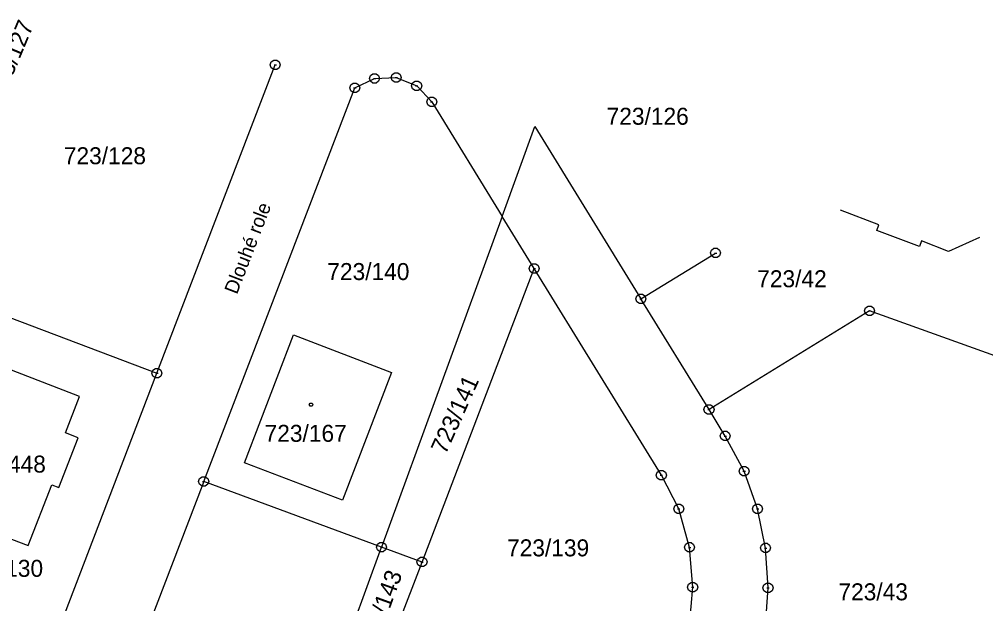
# Model space of a CAD drawing. Extents: x -759060 to -757386, y -1172273 to -1170948.
# Drawn here: x -757575.7 to -757479, y -1171045.6 to -1170987.1 of the extents above; entities that cross this region are included whole.
import ezdxf

# ---------------------------------------------------------------- set-up
doc = ezdxf.new("R2010")
doc.units = 0
for name, color, linetype in [('Vrstva 1', 7, 'Continuous'), ('Vrstva 12', 7, 'Continuous'), ('Vrstva 2', 7, 'Continuous'), ('Vrstva 5', 7, 'Continuous'), ('Vrstva 7', 7, 'Continuous'), ('Vrstva 8', 7, 'Continuous')]:
    doc.layers.add(name, color=color, linetype=linetype)

msp = doc.modelspace()

# ---------------------------------------------------------------- linework, layer by layer
at = {"layer": 'Vrstva 1'}
for p, q in [((-757561.93, -1171022.55), (-757550.09, -1170991.69)), ((-757550.09, -1170991.69), (-757550.09, -1170991.69)), ((-757550.09, -1170991.69), (-757550.09, -1170991.69)), ((-757542.14, -1170994), (-757540.16, -1170993.05)), ((-757540.16, -1170993.05), (-757537.99, -1170992.96)), ((-757537.99, -1170992.96), (-757535.95, -1170993.79)), ((-757557.25, -1171033.38), (-757542.14, -1170994)), ((-757535.95, -1170993.79), (-757534.44, -1170995.39)), ((-757534.44, -1170995.39), (-757527.39, -1171006.85)), ((-757527.39, -1171006.85), (-757524.12, -1170997.86)), ((-757524.12, -1170997.86), (-757513.51, -1171015.11)), ((-757524.12, -1170997.86), (-757524.12, -1170997.86)), ((-757524.12, -1170997.86), (-757524.12, -1170997.86)), ((-757489.72, -1171007.7), (-757493.56, -1171006.23)), ((-757493.56, -1171006.23), (-757493.56, -1171006.23)), ((-757527.39, -1171006.85), (-757539.46, -1171039.95)), ((-757524.19, -1171012.07), (-757527.39, -1171006.85)), ((-757489.93, -1171008.26), (-757489.72, -1171007.7)), ((-757485.65, -1171009.87), (-757489.93, -1171008.26)), ((-757479.64, -1171008.96), (-757482.75, -1171010.35)), ((-757479.64, -1171008.96), (-757479.64, -1171008.96)), ((-757485.46, -1171009.3), (-757485.65, -1171009.87)), ((-757482.75, -1171010.35), (-757485.46, -1171009.3)), ((-757513.51, -1171015.11), (-757506.05, -1171010.52)), ((-757506.05, -1171010.52), (-757506.05, -1171010.52)), ((-757535.41, -1171041.44), (-757524.19, -1171012.07)), ((-757511.47, -1171032.75), (-757524.19, -1171012.07)), ((-757583.3, -1171014.44), (-757561.93, -1171022.55)), ((-757506.7, -1171026.18), (-757513.51, -1171015.11)), ((-757490.64, -1171016.31), (-757506.7, -1171026.18)), ((-757470.02, -1171023.71), (-757490.64, -1171016.31)), ((-757553.18, -1171031.5), (-757548.28, -1171018.7)), ((-757548.28, -1171018.7), (-757538.48, -1171022.46)), ((-757569.69, -1171024.87), (-757577.51, -1171021.85)), ((-757571.92, -1171048.59), (-757561.93, -1171022.55)), ((-757538.48, -1171022.46), (-757543.37, -1171035.25)), ((-757571.08, -1171028.52), (-757569.69, -1171024.87)), ((-757505.08, -1171028.83), (-757506.7, -1171026.18)), ((-757571.76, -1171033.99), (-757569.83, -1171029.01)), ((-757569.83, -1171029.01), (-757571.08, -1171028.52)), ((-757503.19, -1171032.35), (-757505.08, -1171028.83)), ((-757543.37, -1171035.25), (-757553.18, -1171031.5)), ((-757509.73, -1171036.12), (-757511.47, -1171032.75)), ((-757501.85, -1171036.12), (-757503.19, -1171032.35)), ((-757574.81, -1171039.78), (-757572.46, -1171033.73)), ((-757572.46, -1171033.73), (-757571.76, -1171033.99)), ((-757557.25, -1171033.38), (-757565.99, -1171056.19)), ((-757539.46, -1171039.95), (-757557.25, -1171033.38)), ((-757508.65, -1171039.97), (-757509.73, -1171036.12)), ((-757501.04, -1171040.04), (-757501.85, -1171036.12)), ((-757583.62, -1171036.44), (-757574.81, -1171039.78)), ((-757554.12, -1171080.18), (-757539.46, -1171039.95)), ((-757535.41, -1171041.44), (-757539.46, -1171039.95)), ((-757508.34, -1171043.96), (-757508.65, -1171039.97)), ((-757500.8, -1171044.03), (-757501.04, -1171040.04)), ((-757537.8, -1171047.68), (-757535.41, -1171041.44)), ((-757508.66, -1171047.95), (-757508.34, -1171043.96)), ((-757501.06, -1171048.02), (-757500.8, -1171044.03))]:
    msp.add_line(p, q, dxfattribs=at)
at = {"layer": 'Vrstva 12'}
for p, q in [((-757489.72, -1171007.7), (-757493.56, -1171006.23)), ((-757493.56, -1171006.23), (-757493.56, -1171006.23)), ((-757489.93, -1171008.26), (-757489.72, -1171007.7)), ((-757485.65, -1171009.87), (-757489.93, -1171008.26)), ((-757479.64, -1171008.96), (-757482.75, -1171010.35)), ((-757479.64, -1171008.96), (-757479.64, -1171008.96)), ((-757485.46, -1171009.3), (-757485.65, -1171009.87)), ((-757482.75, -1171010.35), (-757485.46, -1171009.3)), ((-757553.18, -1171031.5), (-757548.28, -1171018.7)), ((-757548.28, -1171018.7), (-757538.48, -1171022.46)), ((-757569.69, -1171024.87), (-757577.51, -1171021.85)), ((-757538.48, -1171022.46), (-757543.37, -1171035.25)), ((-757571.08, -1171028.52), (-757569.69, -1171024.87)), ((-757571.76, -1171033.99), (-757569.83, -1171029.01)), ((-757569.83, -1171029.01), (-757571.08, -1171028.52)), ((-757543.37, -1171035.25), (-757553.18, -1171031.5)), ((-757574.81, -1171039.78), (-757572.46, -1171033.73)), ((-757572.46, -1171033.73), (-757571.76, -1171033.99)), ((-757583.62, -1171036.44), (-757574.81, -1171039.78))]:
    msp.add_line(p, q, dxfattribs=at)
at = {"layer": 'Vrstva 5'}
msp.add_lwpolyline([(-757546.42, -1171025.53), (-757546.33, -1171025.68), (-757546.42, -1171025.83), (-757546.6, -1171025.83), (-757546.69, -1171025.68), (-757546.6, -1171025.53)], close=True, dxfattribs=at)
at = {"layer": 'Vrstva 8'}
for p, q in [((-757550.21, -1170991.69), (-757549.97, -1170991.69)), ((-757540.28, -1170993.05), (-757540.04, -1170993.05)), ((-757538.11, -1170992.96), (-757537.87, -1170992.96)), ((-757542.26, -1170994), (-757542.02, -1170994)), ((-757536.07, -1170993.79), (-757535.83, -1170993.79)), ((-757534.56, -1170995.39), (-757534.32, -1170995.39)), ((-757506.17, -1171010.52), (-757505.93, -1171010.52)), ((-757524.31, -1171012.07), (-757524.07, -1171012.07)), ((-757513.63, -1171015.11), (-757513.39, -1171015.11)), ((-757490.76, -1171016.31), (-757490.52, -1171016.31)), ((-757562.05, -1171022.55), (-757561.81, -1171022.55)), ((-757506.82, -1171026.18), (-757506.58, -1171026.18)), ((-757505.2, -1171028.83), (-757504.96, -1171028.83)), ((-757511.59, -1171032.75), (-757511.35, -1171032.75)), ((-757503.31, -1171032.35), (-757503.07, -1171032.35)), ((-757557.37, -1171033.38), (-757557.13, -1171033.38)), ((-757509.85, -1171036.12), (-757509.61, -1171036.12)), ((-757501.97, -1171036.12), (-757501.73, -1171036.12)), ((-757539.58, -1171039.95), (-757539.34, -1171039.95)), ((-757508.77, -1171039.97), (-757508.53, -1171039.97)), ((-757501.16, -1171040.04), (-757500.92, -1171040.04)), ((-757535.53, -1171041.44), (-757535.29, -1171041.44)), ((-757508.46, -1171043.96), (-757508.22, -1171043.96)), ((-757500.92, -1171044.03), (-757500.68, -1171044.03))]:
    msp.add_line(p, q, dxfattribs=at)
for points in [[(-757549.94, -1170991.21), (-757549.69, -1170991.39), (-757549.59, -1170991.68), (-757549.69, -1170991.97), (-757549.94, -1170992.15), (-757550.25, -1170992.15), (-757550.5, -1170991.97), (-757550.6, -1170991.68), (-757550.5, -1170991.39), (-757550.25, -1170991.21)], [(-757540.01, -1170992.57), (-757539.76, -1170992.75), (-757539.66, -1170993.04), (-757539.76, -1170993.33), (-757540.01, -1170993.51), (-757540.32, -1170993.51), (-757540.57, -1170993.33), (-757540.67, -1170993.04), (-757540.57, -1170992.75), (-757540.32, -1170992.57)], [(-757537.84, -1170992.48), (-757537.59, -1170992.66), (-757537.49, -1170992.95), (-757537.59, -1170993.24), (-757537.84, -1170993.42), (-757538.15, -1170993.42), (-757538.4, -1170993.24), (-757538.5, -1170992.95), (-757538.4, -1170992.66), (-757538.15, -1170992.48)], [(-757541.99, -1170993.52), (-757541.74, -1170993.7), (-757541.64, -1170993.99), (-757541.74, -1170994.28), (-757541.99, -1170994.46), (-757542.3, -1170994.46), (-757542.55, -1170994.28), (-757542.65, -1170993.99), (-757542.55, -1170993.7), (-757542.3, -1170993.52)], [(-757535.8, -1170993.31), (-757535.55, -1170993.49), (-757535.45, -1170993.78), (-757535.55, -1170994.07), (-757535.8, -1170994.25), (-757536.11, -1170994.25), (-757536.36, -1170994.07), (-757536.46, -1170993.78), (-757536.36, -1170993.49), (-757536.11, -1170993.31)], [(-757534.29, -1170994.91), (-757534.04, -1170995.09), (-757533.94, -1170995.38), (-757534.04, -1170995.67), (-757534.29, -1170995.85), (-757534.6, -1170995.85), (-757534.85, -1170995.67), (-757534.95, -1170995.38), (-757534.85, -1170995.09), (-757534.6, -1170994.91)], [(-757505.9, -1171010.04), (-757505.65, -1171010.22), (-757505.55, -1171010.51), (-757505.65, -1171010.8), (-757505.9, -1171010.98), (-757506.21, -1171010.98), (-757506.46, -1171010.8), (-757506.56, -1171010.51), (-757506.46, -1171010.22), (-757506.21, -1171010.04)], [(-757524.04, -1171011.59), (-757523.79, -1171011.77), (-757523.69, -1171012.06), (-757523.79, -1171012.35), (-757524.04, -1171012.53), (-757524.35, -1171012.53), (-757524.6, -1171012.35), (-757524.7, -1171012.06), (-757524.6, -1171011.77), (-757524.35, -1171011.59)], [(-757513.36, -1171014.63), (-757513.11, -1171014.81), (-757513.01, -1171015.1), (-757513.11, -1171015.39), (-757513.36, -1171015.57), (-757513.67, -1171015.57), (-757513.92, -1171015.39), (-757514.02, -1171015.1), (-757513.92, -1171014.81), (-757513.67, -1171014.63)], [(-757490.49, -1171015.83), (-757490.24, -1171016.01), (-757490.14, -1171016.3), (-757490.24, -1171016.59), (-757490.49, -1171016.77), (-757490.8, -1171016.77), (-757491.05, -1171016.59), (-757491.15, -1171016.3), (-757491.05, -1171016.01), (-757490.8, -1171015.83)], [(-757561.78, -1171022.07), (-757561.53, -1171022.25), (-757561.43, -1171022.54), (-757561.53, -1171022.83), (-757561.78, -1171023.01), (-757562.09, -1171023.01), (-757562.34, -1171022.83), (-757562.44, -1171022.54), (-757562.34, -1171022.25), (-757562.09, -1171022.07)], [(-757506.55, -1171025.7), (-757506.3, -1171025.88), (-757506.2, -1171026.17), (-757506.3, -1171026.46), (-757506.55, -1171026.64), (-757506.86, -1171026.64), (-757507.11, -1171026.46), (-757507.21, -1171026.17), (-757507.11, -1171025.88), (-757506.86, -1171025.7)], [(-757504.93, -1171028.35), (-757504.68, -1171028.53), (-757504.58, -1171028.82), (-757504.68, -1171029.11), (-757504.93, -1171029.29), (-757505.24, -1171029.29), (-757505.49, -1171029.11), (-757505.59, -1171028.82), (-757505.49, -1171028.53), (-757505.24, -1171028.35)], [(-757511.32, -1171032.27), (-757511.07, -1171032.45), (-757510.97, -1171032.74), (-757511.07, -1171033.03), (-757511.32, -1171033.21), (-757511.63, -1171033.21), (-757511.88, -1171033.03), (-757511.98, -1171032.74), (-757511.88, -1171032.45), (-757511.63, -1171032.27)], [(-757503.04, -1171031.87), (-757502.79, -1171032.05), (-757502.69, -1171032.34), (-757502.79, -1171032.63), (-757503.04, -1171032.81), (-757503.35, -1171032.81), (-757503.6, -1171032.63), (-757503.7, -1171032.34), (-757503.6, -1171032.05), (-757503.35, -1171031.87)], [(-757557.1, -1171032.9), (-757556.85, -1171033.08), (-757556.75, -1171033.37), (-757556.85, -1171033.66), (-757557.1, -1171033.84), (-757557.41, -1171033.84), (-757557.66, -1171033.66), (-757557.76, -1171033.37), (-757557.66, -1171033.08), (-757557.41, -1171032.9)], [(-757509.58, -1171035.64), (-757509.33, -1171035.82), (-757509.23, -1171036.11), (-757509.33, -1171036.4), (-757509.58, -1171036.58), (-757509.89, -1171036.58), (-757510.14, -1171036.4), (-757510.24, -1171036.11), (-757510.14, -1171035.82), (-757509.89, -1171035.64)], [(-757501.7, -1171035.64), (-757501.45, -1171035.82), (-757501.35, -1171036.11), (-757501.45, -1171036.4), (-757501.7, -1171036.58), (-757502.01, -1171036.58), (-757502.26, -1171036.4), (-757502.36, -1171036.11), (-757502.26, -1171035.82), (-757502.01, -1171035.64)], [(-757539.31, -1171039.47), (-757539.06, -1171039.65), (-757538.96, -1171039.94), (-757539.06, -1171040.23), (-757539.31, -1171040.41), (-757539.62, -1171040.41), (-757539.87, -1171040.23), (-757539.97, -1171039.94), (-757539.87, -1171039.65), (-757539.62, -1171039.47)], [(-757508.5, -1171039.49), (-757508.25, -1171039.67), (-757508.15, -1171039.96), (-757508.25, -1171040.25), (-757508.5, -1171040.43), (-757508.81, -1171040.43), (-757509.06, -1171040.25), (-757509.16, -1171039.96), (-757509.06, -1171039.67), (-757508.81, -1171039.49)], [(-757500.89, -1171039.56), (-757500.64, -1171039.74), (-757500.54, -1171040.03), (-757500.64, -1171040.32), (-757500.89, -1171040.5), (-757501.2, -1171040.5), (-757501.45, -1171040.32), (-757501.55, -1171040.03), (-757501.45, -1171039.74), (-757501.2, -1171039.56)], [(-757535.26, -1171040.96), (-757535.01, -1171041.14), (-757534.91, -1171041.43), (-757535.01, -1171041.72), (-757535.26, -1171041.9), (-757535.57, -1171041.9), (-757535.82, -1171041.72), (-757535.92, -1171041.43), (-757535.82, -1171041.14), (-757535.57, -1171040.96)], [(-757508.19, -1171043.48), (-757507.94, -1171043.66), (-757507.84, -1171043.95), (-757507.94, -1171044.24), (-757508.19, -1171044.42), (-757508.5, -1171044.42), (-757508.75, -1171044.24), (-757508.85, -1171043.95), (-757508.75, -1171043.66), (-757508.5, -1171043.48)], [(-757500.65, -1171043.55), (-757500.4, -1171043.73), (-757500.3, -1171044.02), (-757500.4, -1171044.31), (-757500.65, -1171044.49), (-757500.96, -1171044.49), (-757501.21, -1171044.31), (-757501.31, -1171044.02), (-757501.21, -1171043.73), (-757500.96, -1171043.55)]]:
    msp.add_lwpolyline(points, close=True, dxfattribs=at)

# ---------------------------------------------------------------- texts
at = {"layer": 'Vrstva 2'}
for s, rotation, p in [('723/127', 67.20795, (-757577.399, -1170995.257)), ('723/141', 65.71826, (-757533.052, -1171030.751)), ('723/143', 70.01544, (-757540.166, -1171050.37))]:
    msp.add_text(s, height=1.7, rotation=rotation, dxfattribs=at).set_placement(p)
for s, p in [('723/126', (-757516.948, -1170997.68)), ('723/128', (-757571.248, -1171001.63)), ('723/140', (-757544.891, -1171013.22)), ('723/42', (-757501.887, -1171013.94)), ('723/167', (-757551.164, -1171029.41)), ('723/448', (-757581.262, -1171032.49)), ('723/139', (-757526.911, -1171040.87)), ('723/130', (-757581.538, -1171042.92)), ('723/43', (-757493.76, -1171045.27))]:
    msp.add_text(s, height=1.7, dxfattribs=at).set_placement(p)
at = {"layer": 'Vrstva 7'}
msp.add_text('Dlouhé role', height=1.4, rotation=68.86953, dxfattribs=at).set_placement((-757553.931, -1171014.727))

doc.saveas('drawing.dxf')
